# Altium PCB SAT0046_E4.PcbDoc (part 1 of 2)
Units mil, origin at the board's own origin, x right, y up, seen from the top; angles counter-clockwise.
Board outline 1588 x 1588 mil, 4 copper layers (Top Layer, GND, Inner 1, Bottom Layer); 110 components, 70 nets, 285 pads, 141 vias.
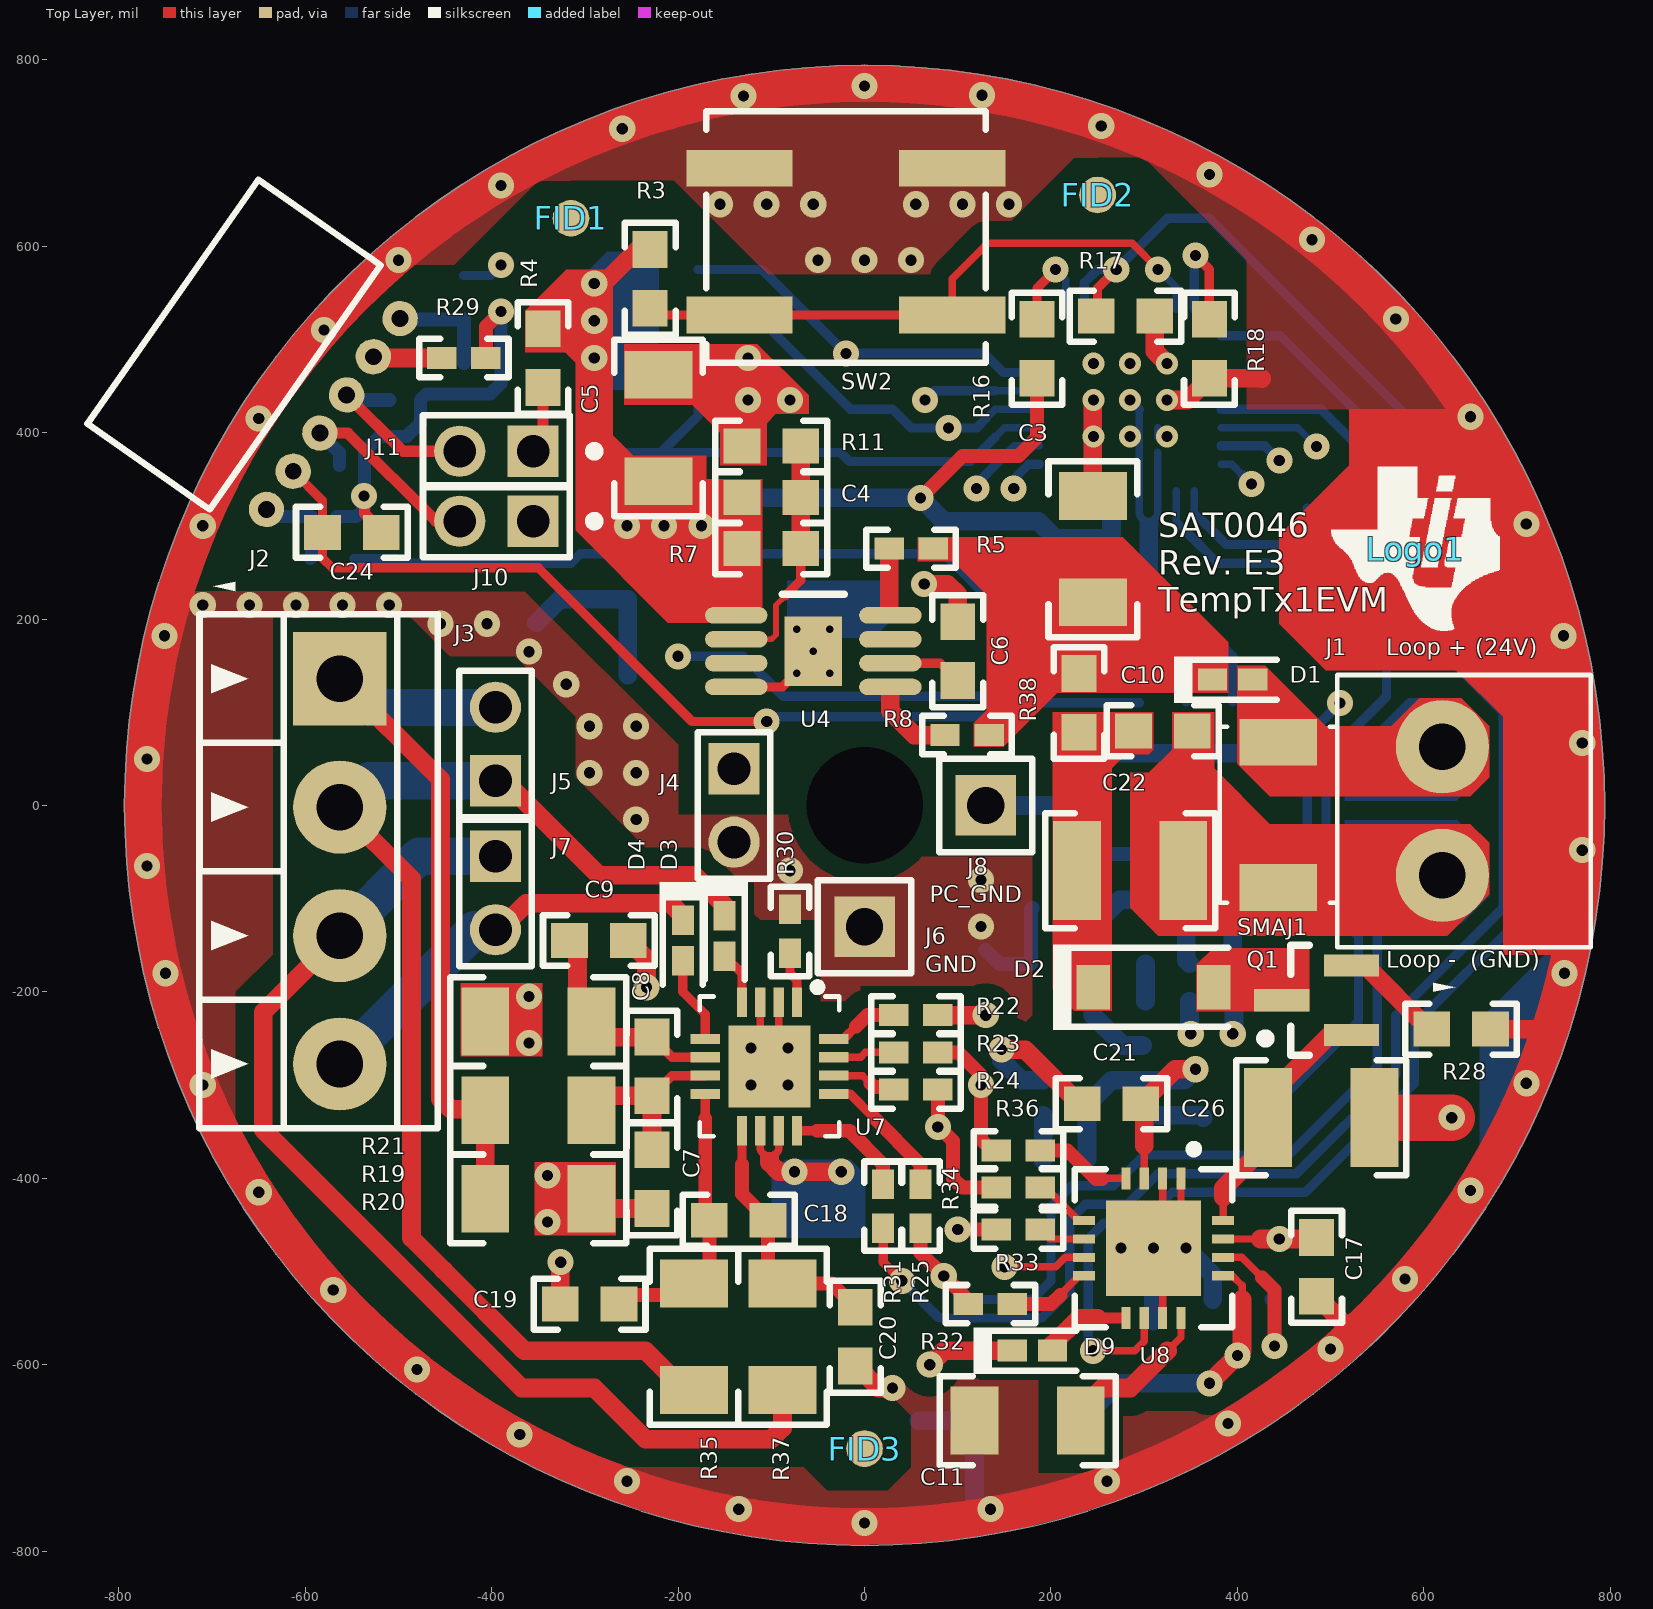
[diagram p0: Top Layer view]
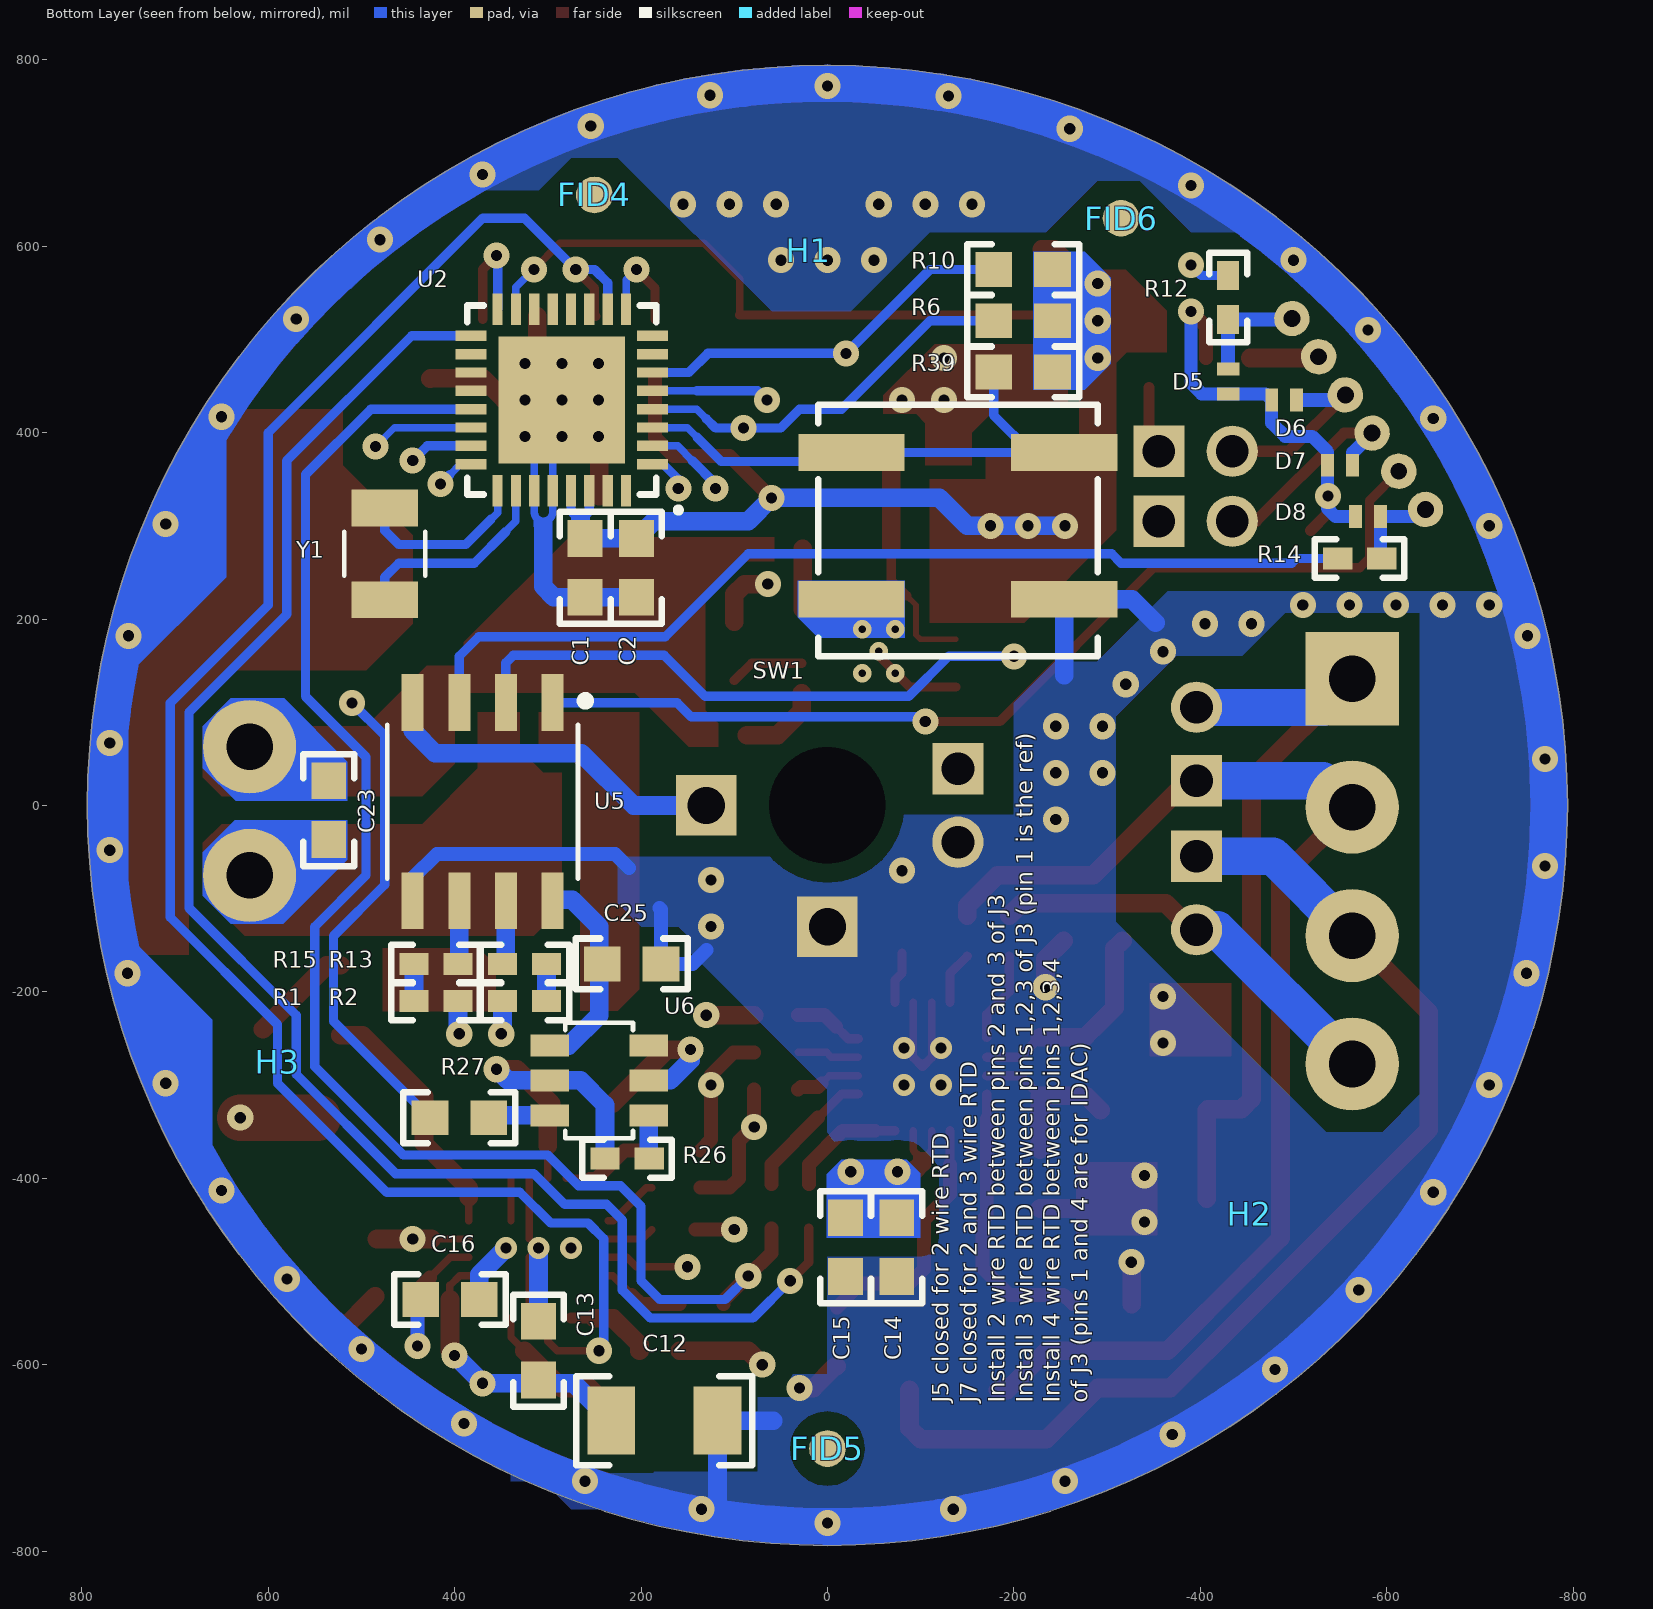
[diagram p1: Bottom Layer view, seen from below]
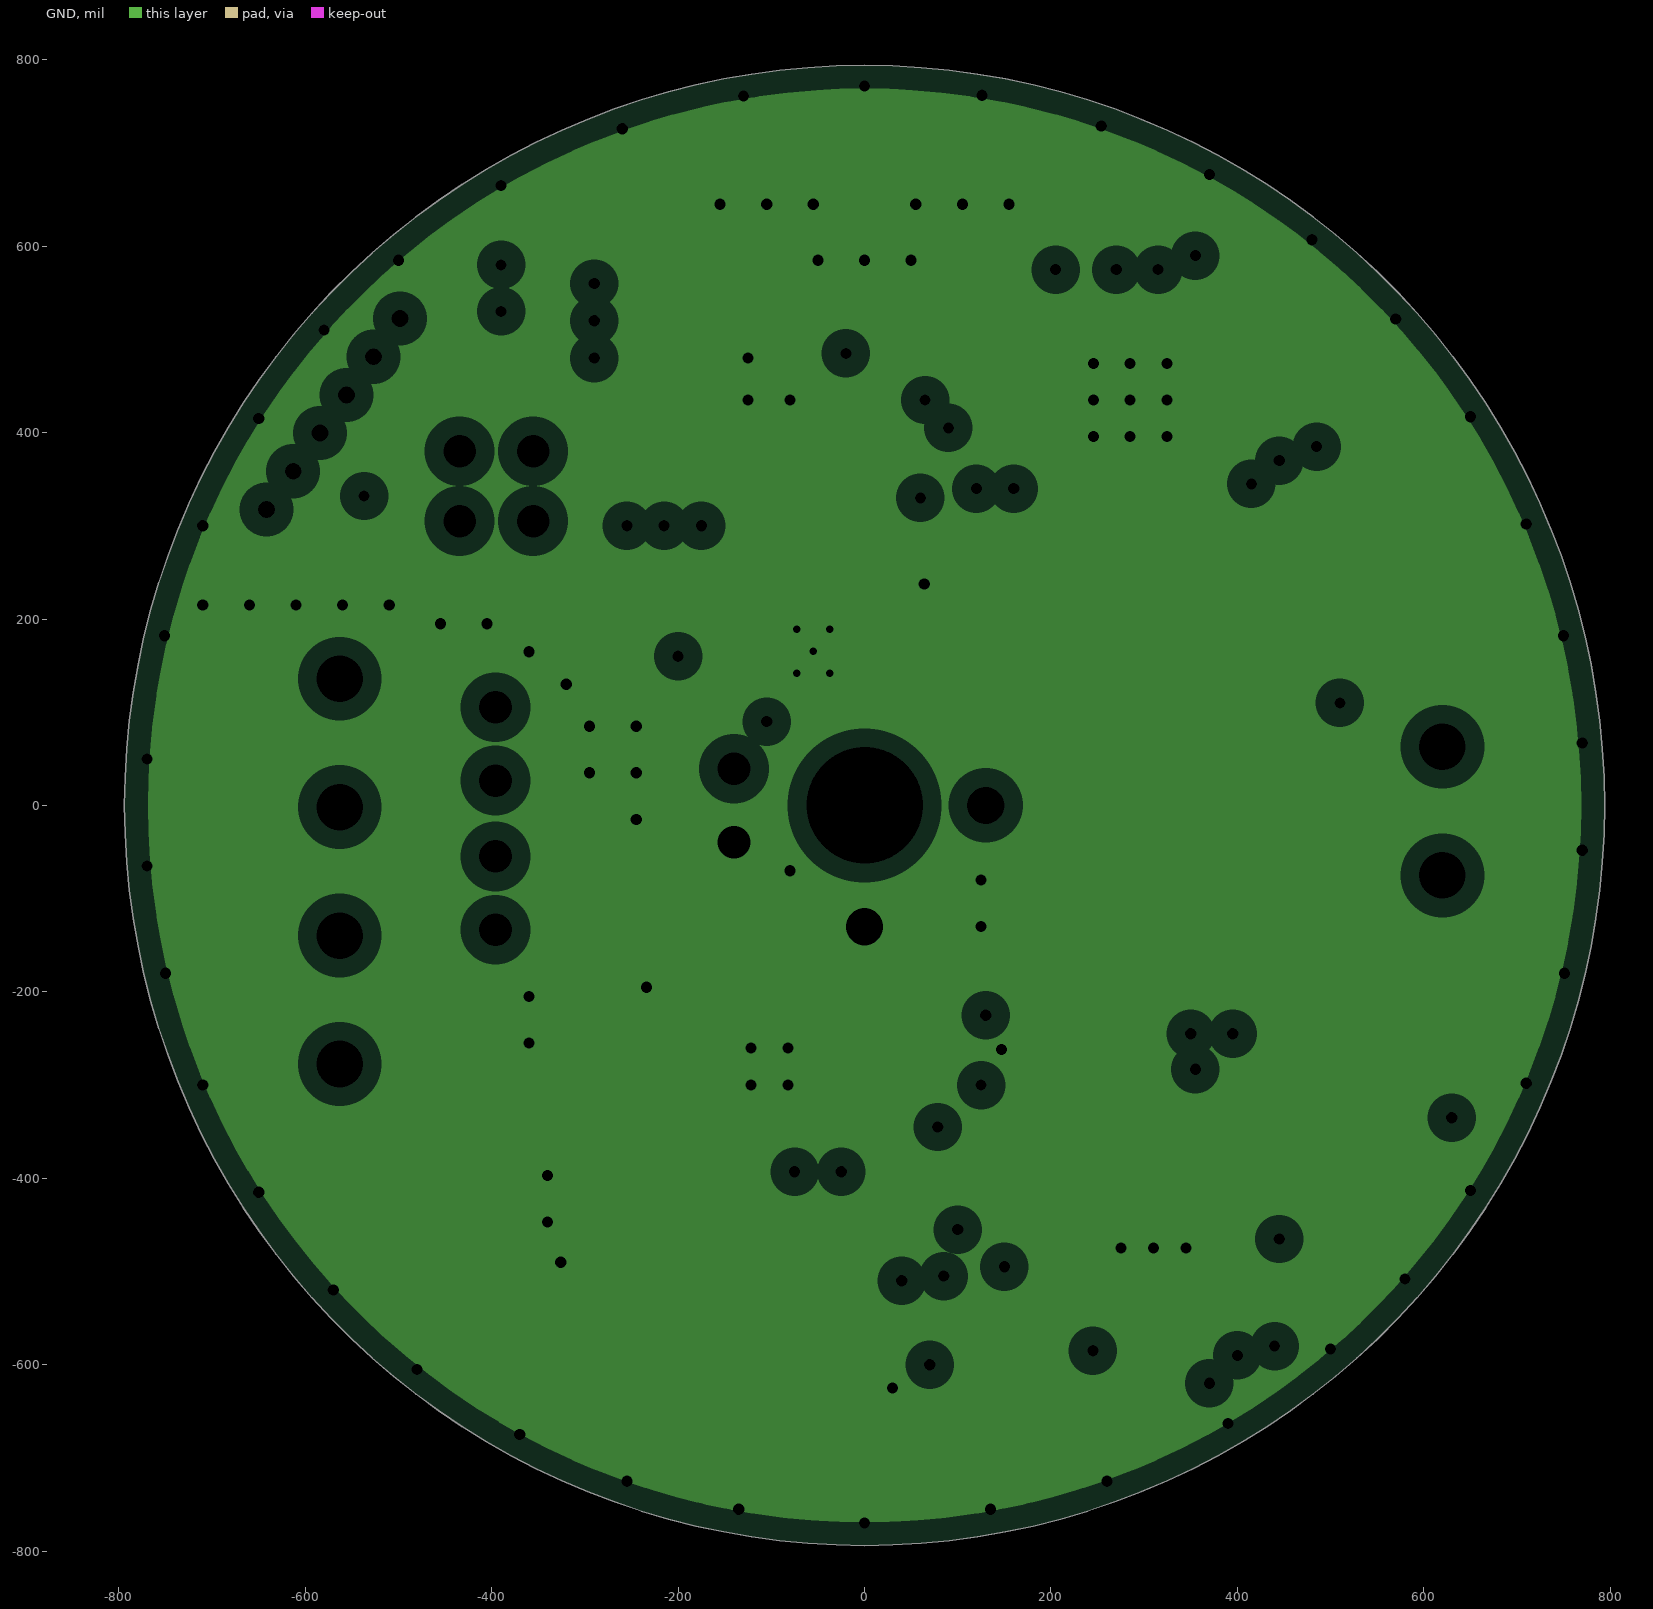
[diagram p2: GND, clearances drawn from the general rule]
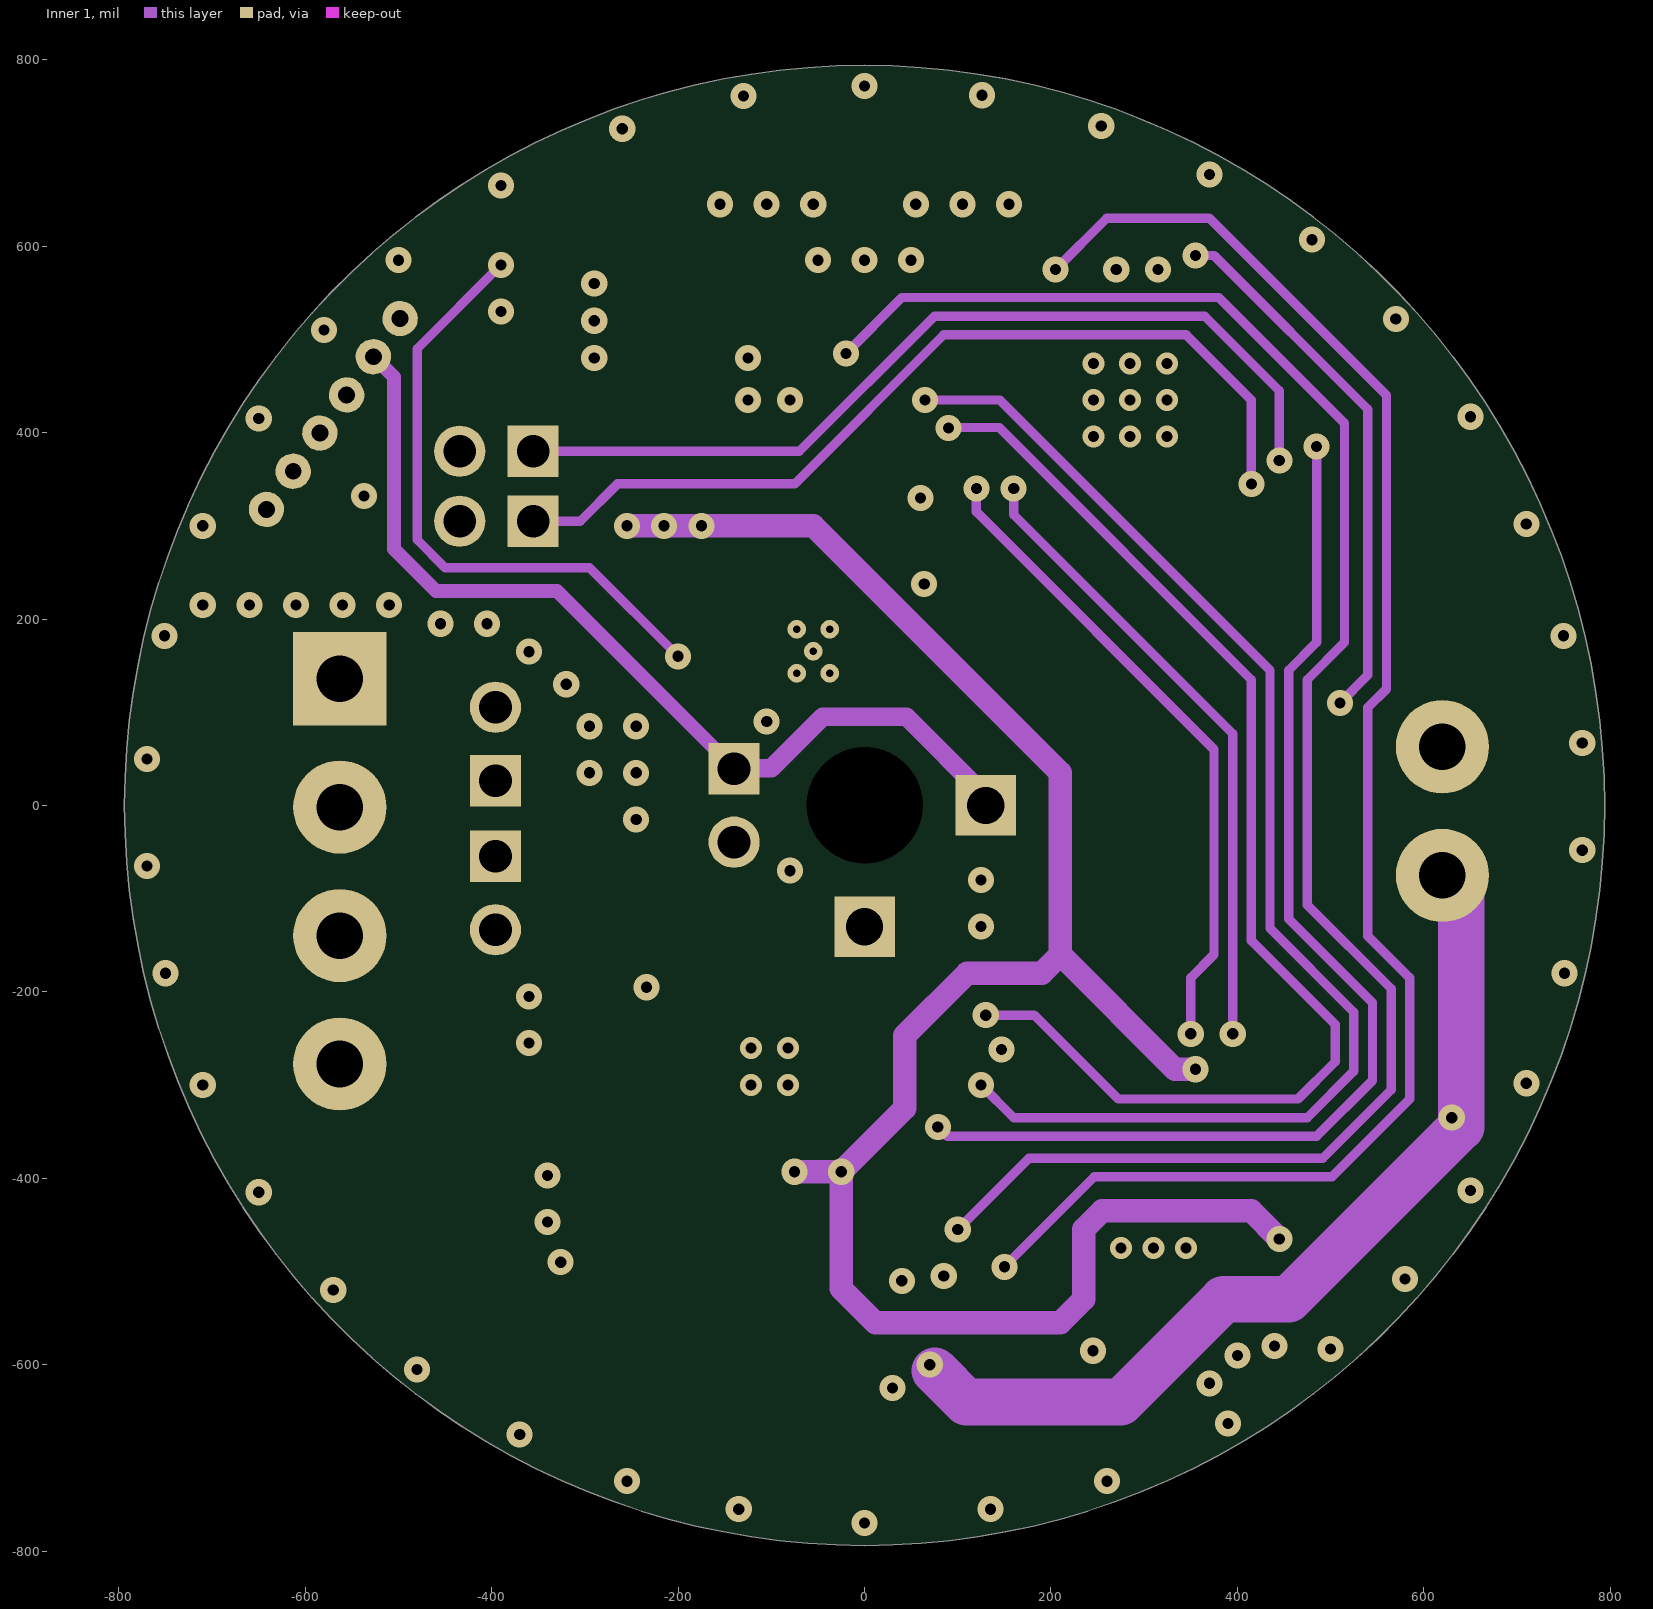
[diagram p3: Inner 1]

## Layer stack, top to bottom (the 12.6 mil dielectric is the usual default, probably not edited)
Top Layer: signal copper 1.4
Dielectric: core 12.6, 370HR, Dk 4.8
GND: plane copper 1.4, net GND
Dielectric: prepreg 12.6, 370HR, Dk 4.8
Inner 1: signal copper 1.4
Dielectric: core 12.6, 370HR, Dk 4.8
Bottom Layer: signal copper 1.4

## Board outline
0,-794 cw(c0,0) -794,0 cw(c0,0) 0,794 cw(c0,0) 794,0 cw(c0,0)

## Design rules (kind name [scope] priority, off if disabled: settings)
AcuteAngle [All] p1: minimum=4.50000000000000E+0001 checktracksonly=FALSE
AssemblyTestPointUsage [All] p1: valid=2
Clearance Clearance_GND_Poly [InPolygon] p1: gap=20
Clearance U2 [InComponent('U2')] p2: gap=8.6
Clearance NetC4_1 [InNet('NetC4_1')] p3: gap=6.09
Clearance U4 [InComponent('U4')] p4: gap=7.87
Clearance U7 [InComponent('U7')] p5: gap=8.6
Clearance U8 [InComponent('U8')] p6: gap=9.8
Clearance Clearance_BoardEdge_MountingHoles [OnCopper and InComponentClass('Mounting Holes') vs IsKeepOut] p7 off: gap=40
Clearance Clearance_BoardEdge_Poly [OnCopper and InPoly vs IsKeepOut] p8 off: gap=25
Clearance Clearance_BoardEdge [OnCopper and Not InComponentClass('Logo') and not InComponentClass('FiducialMark') and not InRegion(1000,500,4000,800) and Not IsKeepout vs IsKeepOut] p9 off: gap=20
Clearance [All] p10: gap=10
ComponentClearance ComponentClearance_Logo [InComponentClass(Logo)] p1 off: gap=50 collisioncheckmode=3 verticalgap=10 showdistances=FALSE
ComponentClearance ComponentClearance_ScrewToNut [(HasFootprint('NY PMS 440 0025 PH')) vs (HasFootprint('Keystone_1902C'))] p2 off: gap=5 collisioncheckmode=3 verticalgap=10 showdistances=FALSE
ComponentClearance ComponentClearance_MountingHoles [InComponentClass('Mounting Holes')] p3 off: gap=250 collisioncheckmode=3 verticalgap=100000 showdistances=FALSE
ComponentClearance ComponentClearance_SmallPassives [HasFootprint('0201*') or HasFootprint('0402*') or HasFootprint('0508') or HasFootprint('0603*') or HasFootprint('0612') or HasFootprint('0805*') or HasFootprint('0815*') or HasFootprint('0830*') or HasFootprint('1206*') or HasFootprint('1210*') or HasFootprint('1808*') or HasFootprint('1812*') or HasFootprint('1825*') or HasFootprint('2010*') or HasFootprint('2220*') or HasFootprint('2225*') or HasFootprint('2512*') or HasFootprint('2728*') or HasFootprint('3518*') vs HasFootprint('0201*') or HasFootprint('0402*') or HasFootprint('0508') or HasFootprint('0603*') or HasFootprint('0612') or HasFootprint('0805*') or HasFootprint('0815*') or HasFootprint('0830*') or HasFootprint('1206*') or HasFootprint('1210*') or HasFootprint('1808*') or HasFootprint('1812*') or HasFootprint('1825*') or HasFootprint('2010*') or HasFootprint('2220*') or HasFootprint('2225*') or HasFootprint('2512*') or HasFootprint('2728*') or HasFootprint('3518*')] p4 off: gap=20 collisioncheckmode=3 verticalgap=10 showdistances=FALSE
ComponentClearance ComponentClearance_THtoSMT [IsThruComponent vs IsSMTComponent] p5 off: gap=100 collisioncheckmode=3 verticalgap=100000 showdistances=FALSE
ComponentClearance ComponentClearance_THtoTH [IsThruComponent vs IsThruComponent] p6 off: gap=118.11 collisioncheckmode=3 verticalgap=100000 showdistances=FALSE
ComponentClearance [All] p7 off: gap=40 collisioncheckmode=3 verticalgap=10 showdistances=FALSE
DiffPairsRouting [All] p1: maxlimit=100 minlimit=10 mostfreqgap=10 maxuncoupledlength=1000
FabricationTestPointUsage TestPointUsage [All] p1: valid=2 allowmultiple=FALSE
FabricationTestpoint Testpoint [All] p1: side=3 testpointundercomponent=TRUE minsize=40 maxsize=100 preferedsize=60 minholesize=0 maxholesize=40 preferedholesize=32 testpointgrid=1 allowsidetop=TRUE allowsidebottom=TRUE usegrid=TRUE gridtolerance=0.01
FanoutControl Fanout_LCC [IsLCC] p1: bgadir=Out bgaviamode=Centered fanoutstyle=Auto fanoutdirection=Alternating viagrid=1 // Fanout_LCC (Default Rule)
FanoutControl Fanout_BGA [IsBGA] p2: bgadir=Out bgaviamode=Centered fanoutstyle=Auto fanoutdirection=Alternating viagrid=1 // Fanout_BGA (Default Rule)
FanoutControl Fanout_Default [All] p4: bgadir=Out bgaviamode=Centered fanoutstyle=Auto fanoutdirection=Alternating viagrid=1 // Fanout_Default (Default Rule)
FanoutControl Fanout_Small [(CompPinCount < 5)] p5: bgadir=Out bgaviamode=Centered fanoutstyle=Auto fanoutdirection=OutThenIn viagrid=1 // Fanout_Small (Default Rule)
HoleSize "U4 Hole" [(InNet('GND') AND InComponent('U4'))] p1: absolutevalues=TRUE maxlimit=100 minlimit=5 maxpercent=80.000 minpercent=20.000
HoleSize [All] p2: absolutevalues=TRUE maxlimit=251 minlimit=8 maxpercent=80.000 minpercent=20.000
MinimumAnnularRing "U8 AnnularRing" [(InNet('GND') AND InComponent('U8'))] p1: minimumring=5
MinimumAnnularRing "U2 AnnularRing" [(InNet('GND') AND InComponent('U2'))] p2: minimumring=5.9
MinimumAnnularRing "U7 AnnularRing" [(InNet('GND') AND InComponent('U7'))] p3: minimumring=3
MinimumAnnularRing "U4 AnnularRing" [(InNet('GND') AND InComponent('U4'))] p4: minimumring=3
MinimumAnnularRing [All] p5: minimumring=5
MinimumSolderMaskSliver MinimumSolderMaskSliver_Logo [InComponentClass('Logo') vs InComponentClass('Logo')] p1: minsoldermaskwidth=0.7
MinimumSolderMaskSliver [All] p2: minsoldermaskwidth=5
PlaneClearance [All] p1: clearance=20
PlaneConnect [All] p1: planeconnectstyle=Direct reliefexpansion=10 reliefentries=4 reliefconductorwidth=10 reliefairgap=10
PolygonConnect [All] p1: connectstyle=Direct reliefconductorwidth=10 reliefentries=4 polygonreliefangle="90 Angle" airgapwidth=10
RoutingVias [All] p1: holewidth=16 width=34 viastyle="Through Hole" minholewidth=5 minwidth=15 maxholewidth=40 maxwidth=65
SMDToCorner [All] p1 off: distance=30000
SilkToSilkClearance [All] p1: silktosilkclearance=0
SilkscreenOverComponentPads [All] p1: minsilkscreentomaskgap=1
SolderMaskExpansion [All] p1: expansion=1
Width [All] p1: maxlimit=100 minlimit=6 preferedwidth=10 checkconnectedcopper=TRUE
13 further rules are at their usual default settings.

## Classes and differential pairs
component class Header: J6 J8
component class Logo: Logo1
component class Hardware: FID1 FID2 FID3 FID4 FID5 FID6 H1 H2 H3 Logo1 ZZ1 ZZ2 ZZ3 ZZ4 ZZ5 ZZ6
component class FiducialMark: FID1 FID2 FID3 FID4 FID5 FID6
component class AssemblyNote: ZZ1 ZZ2 ZZ3 ZZ4 ZZ5 ZZ6
component class SAT0046_E3_Temp_Transmitter_System: C3 C4 C5 C6 C7 C8 C9 C10 C11 C12 C13 C14 C15 C16 C17 C18 C19 C20 C21 C22 C23 C26 D1 D2 D3 D4 D9 J1 J3 J5 J7 Q1 R5 R7 R8 R11 R19 R20 R21 R22 R23 R24 R25 R28 R30 R31 R32 R33 R34 R35 R36 R37 R38 SMAJ1 U4 U7 U8
component class SAT0046_E3_MSP430: C1 C2 C24 C25 D5 D6 D7 D8 J2 J4 J6 J8 J10 J11 R1 R2 R3 R4 R6 R10 R12 R13 R14 R15 R16 R17 R18 R26 R27 R29 R39 SW1 SW2 U2 U5 U6 Y1

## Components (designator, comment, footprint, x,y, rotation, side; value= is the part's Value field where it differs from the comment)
C1 "C0603X104K4RACTU" 0603 260,255 r270 bottom
C2 "C0603X104K4RACTU" 0603 205,255 r90 bottom
C3 "12065C334KAT2A" 1206 245,275 r90 top
C4 "C0603C103J5RACTU" 0603 -100,330.5 r180 top
C5 "GRM31CR71C106KAC7L" 1206 -221,405 r90 top
C6 "C0603C103J5RACTU" 0603 100,165.5 r90 top
C7 "Used in BOM report" 0603 -228,-401 r270 top
C8 "C0603C183K1RACTU" 0603 -228,-280 r90 top
C9 "Used in BOM report" 0603 -285,-145 r0 top
C10 "C0603C103J5RACTU" 0603 320,80 r0 top
C11 "GRM31MR71H394KA01L" 1206 175,-660 r180 top
C12 "C1206C224J5RACTU" 1206 175,-660 r180 bottom
C13 "C0603C682J5RACTU" 0603 310,-585 r90 bottom
C14 "C0603X104K4RACTU" 0603 -74.4,-473.98 r270 bottom
C15 "C0603X104K4RACTU" 0603 -19.4,-473.98 r270 bottom
C16 "C0603C102J5RACTU" 0603 405,-530 r180 bottom
C17 "C0603X104K4RACTU" 0603 485,-495 r270 top
C18 "C0603C273K1RACTU" 0603 -135,-445 r180 top
C19 "Used in BOM report" 0603 -295,-535 r180 top
C20 "Used in BOM report" 0603 -10,-570 r270 top
C21 "C0603X104K4RACTU" 0603 265,-320 r180 top
C22 "GRM32ER71H106KA12L" 1210 285,-70 r0 top
C23 "C1608X7R2A103K" 0603 535,-5 r270 bottom
C24 "C0603X104K4RACTU" 0603 -550,293 r0 top
C25 "C0603X104K4RACTU" 0603 210,-170 r180 bottom
C26 "GRM32ER71H106KA12L" 1210 490,-335 r0 top
D1 "ZHCS350TA" SOD-523 395,135 r0 top
D2 "MMSZ4686T1G" SOD-123 310,-195 r0 top
D3 "ZHCS350TA" SOD-523 -150,-140 r270 top
D4 "ZHCS350TA" SOD-523 -195,-145 r270 top
D5 "TPD1E10B06DPYR" DPY0002A_N -430,455 r270 bottom
D6 "TPD1E10B06DPYR" DPY0002A_N -490,435 r0 bottom
D7 "TPD1E10B06DPYR" DPY0002A_N -550,365 r0 bottom
D8 "TPD1E10B06DPYR" DPY0002A_N -580,310 r0 bottom
D9 "ZHCS350TA" SOD-523 180,-585 r0 top
FID1 "Fiducial" Fiducial10-20#1 -315,630 r0 top
FID2 "Fiducial" Fiducial10-20#1 250,655 r0 top
FID3 "Fiducial" Fiducial10-20#1 0,-690 r0 top
FID4 "Fiducial" Fiducial10-20#2 205,675 r180 bottom
FID5 "Fiducial" Fiducial10-20#1 0,-690 r180 bottom
FID6 "Fiducial" Fiducial10-20#3 -270,650 r180 bottom
H1 "SJ61A1" Bumpon_SJ61A1 20,595 r180 bottom
H2 "SJ61A1" Bumpon_SJ61A1 -453,-438 r180 bottom
H3 "SJ61A1" Bumpon_SJ61A1 590,-275 r180 bottom
J1 "ED555/2DS" TERM_BLK_ED555-2DS 620,-75 r90 top
J2 "851-43-006-20-001000" CONN_851-43-006-20-001000 -570,420 r235 top
J3 "ED555/4DS" TERM_BLK_ED555-4DS -563,136 r270 top
J4 "TMM-102-01-T-S" CONN_TMM-102-01-T-S -140,0 r270 top
J5 "TMM-102-01-T-S" CONN_TMM-102-01-T-S -396,66 r90 top
J6 "TSW-101-07-G-S" TSW-101-07-G-S 0,-130 r0 top
J7 "TMM-102-01-T-S" CONN_TMM-102-01-T-S -396,-94 r270 top
J8 "TSW-101-07-G-S" TSW-101-07-G-S 130,0 r0 top
J10 "TMM-102-01-T-S" CONN_TMM-102-01-T-S -395,305 r180 top
J11 "TMM-102-01-T-S" CONN_TMM-102-01-T-S -395,380 r180 top
Logo1 "Texas Instruments" TI_Symbol_Overlay_Small 591,275 r0 top
Q1 "MMBT3904" SOT-23 485,-209 r180 top
R1 "CRCW04020000Z0ED" 0402 420,-210 r0 bottom
R2 "CRCW04020000Z0ED" 0402 325,-210 r180 bottom
R3 "RT0603BRD07100KL" 0603 -230,565 r90 top
R4 "RG1608P-4752-B-T5" 0603 -345,480 r90 top
R5 "CRCW04020000Z0ED" 0402 50,275.5 r0 top
R6 "RT0603BRD07100KL" 0603 -210,520 r180 bottom
R7 "RC0603FR-0721KL" 0603 -100,275.5 r180 top
R8 "CRCW04020000Z0ED" 0402 110,75.5 r180 top
R10 "RT0603BRD07100KL" 0603 -210,575 r180 bottom
R11 "RC0603FR-0712KL" 0603 -100,385.5 r0 top
R12 "CRCW04020000Z0ED" 0402 -430,545 r90 bottom
R13 "CRCW04020000Z0ED" 0402 325,-170 r180 bottom
R14 "CRCW04020000Z0ED" 0402 -571,265 r0 bottom
R15 "CRCW04020000Z0ED" 0402 420,-170 r0 bottom
R16 "RT0603BRD07100KL" 0603 185,490 r270 top
R17 "RT0603BRD07100KL" 0603 280,525 r180 top
R18 "RT0603BRD07100KL" 0603 370,490 r90 top
R19 "ERA-8AEB4121V" 1206 -350,-327 r0 top
R20 "PFC-W1206R-12-3241-B" 1206 -350,-422 r180 top
R21 "ERA-8AEB4121V" 1206 -350,-232 r0 top
R22 "CRCW04020000Z0ED" 0402 55,-225 r0 top
R23 "CRCW04020000Z0ED" 0402 55,-265 r0 top
R24 "CRCW04020000Z0ED" 0402 55,-305 r0 top
R25 "CRCW04020000Z0ED" 0402 60,-430 r270 top
R26 "CRCW04020000Z0ED" 0402 215,-379 r0 bottom
R27 "ERJ-3GEY0R00V" 0603 395,-335 r0 bottom
R28 "CRCW060320R0FKEA" 0603 640,-240 r180 top
R29 "CRCW04020000Z0ED" 0402 -430,480 r180 top
R30 "CRCW040210K0FKEDHP" 0402 -80,-135 r270 top
R31 "CRCW04020000Z0ED" 0402 20,-430 r90 top
R32 "CRCW04020000Z0ED" 0402 135,-535 r0 top
R33 "CRCW04020000Z0ED" 0402 165,-455 r0 top
R34 "CRCW04020000Z0ED" 0402 165,-410 r0 top
R35 "ERA-8AEB4121V" 1206 -183,-570 r90 top
R36 "CRCW04020000Z0ED" 0402 165,-370 r180 top
R37 "ERA-8AEB4121V" 1206 -88,-570 r90 top
R38 "RT0603DRE07200RL" 0603 230,110 r270 top
R39 "RT0603BRD07100KL" 0603 -210,465 r180 bottom
SMAJ1 "SMAJ36CA" SMAJ36CA 444,-10 r90 top
SW1 "KSC222J LFS" "KSC222J LFS" -140,300 r180 bottom
SW2 "KSC222J LFS" "KSC222J LFS" -20,605 r180 top
U2 "MSP430G2513IRHB32R" MSP430G2513IRHB32T 285,435 r270 bottom
U4 "TPS7A4901DGN" DGN0008D_N -55,165.5 r0 top
U5 "ISO7421ED" ISO7421ED 370,4 r0 bottom
U6 "TS5A3160DBVR" TS5A3160DBV 245,-295 r90 bottom
U7 "ADS1220IRVAR" ADS1220IRVAR -102,-280 r180 top
U8 "DAC161S997RGHR" DAC161S997RGHR 310,-475 r0 top
Y1 "NX3215SA-32.768K-STD-MUS-2" XTAL_NX3215SA 475,270 r90 bottom
ZZ1 "Mouse bites are to be located at the 12, 3, 6, and 9 o'clock orientations." AssemblyNote -2100,1630 r0 top
ZZ2 "These assemblies are ESD sensitive, ESD precautions shall be observed." AssemblyNote -2100,1530 r0 top
ZZ3 "These assemblies must be clean and free from flux and all contaminants. Use of no clean flux is not acceptable." AssemblyNote -2100,1430 r0 top
ZZ4 "These assemblies must comply with workmanship standards IPC-A-610 Class 2., unless otherwise specified." AssemblyNote -2100,1330 r0 top
ZZ5 "Assembly: Three bumpons are to be placed where possible to provide a balanced standoff" AssemblyNote -2100,1230 r0 top
ZZ6 "Polygon pour along the board edge is serving as an ESD ring. Soldermask is not to be placed over the ring on either side." AssemblyNote -2100,1130 r0 top

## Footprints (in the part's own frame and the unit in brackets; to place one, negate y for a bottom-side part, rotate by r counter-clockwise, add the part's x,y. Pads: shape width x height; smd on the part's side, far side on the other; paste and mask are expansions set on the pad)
0402 [mm] "0402 from SM-752 data"
  rect 0.8x0.6 smd: 1(-0.6,0) 2(0.6,0)
  silkscreen extent -1.22,-0.52 1.22,0.52, body extent -0.55,-0.3 0.55,0.3, height 0.6
0603 [mm] "0603 from SM-752 data"
  rect 1x0.95 smd: 1(-0.8,0) 2(0.8,0)
  silkscreen extent -1.52,-0.69 1.52,0.69, body extent -0.87,-0.47 0.87,0.47, height 0.85
1206 [mm] "1206 from SM-752 data"
  rect 1.3x1.85 smd: 1(-1.45,0) 2(1.45,0)
  silkscreen extent -2.4,-1.21 2.4,1.21, body extent -1.7,-0.9 1.7,0.9, height 1.35
1210 [mm] "1210 from SM-752 data"
  rect 1.3x2.7 smd: 1(-1.45,0) 2(1.45,0)
  silkscreen extent -2.32,-1.57 2.32,1.57, body extent -1.7,-1.35 1.7,1.35, height 1.35
ADS1220IRVAR [mm] "Low-Power, Low-Noise, 24-Bit, Analog-to-Digital Converter for Small-Signal Sensors"
  rect 0.28x0.8 smd: 1(-0.75,-1.75) 2(-0.25,-1.75) 3(0.25,-1.75) 4(0.75,-1.75) 9(0.75,1.75) 10(0.25,1.75) 11(-0.25,1.75) 12(-0.75,1.75)
  rect 0.8x0.28 smd: 5(1.75,-0.75) 6(1.75,-0.25) 7(1.75,0.25) 8(1.75,0.75) 13(-1.75,0.75) 14(-1.75,0.25) 15(-1.75,-0.25) 16(-1.75,-0.75)
  rect 2.24x2.24 smd: 17(0,0)
  silkscreen extent -1.9,-2.25 1.9,1.91, body extent -1.8,-1.8 1.8,1.8, height 1.01
AssemblyNote [mil] "Assembly Note"
Bumpon_SJ61A1 [mil] "3M Cylindrical Bumpon black"
  round 1 on Mech4: 0(0,0)
  body extent -156,-155 156,156, height 201
CONN_851-43-006-20-001000 [mil] "Mill-Max"
  round 38 hole 18: 1(125,0) 2(75,0) 3(25,0) 4(-25,0) 5(-75,0) 6(-125,0)
  silkscreen extent -160,-210 160,-50, body extent -157,-210 157,8, height 87
CONN_TMM-102-01-T-S [mil] "SAMTEC"
  rect 55x55 hole 35: 1(-39.37,0)
  round 55 hole 35: 2(39.37,0)
  silkscreen extent -79,-39 79,39, body extent -79,-39 79,39, height 185
DAC161S997RGHR [mm] "IC DAC 16BIT SPI/SRL 16WQFN"
  rect 0.25x0.6 smd: 1(0.75,1.9) 2(0.25,1.9) 3(-0.25,1.9) 4(-0.75,1.9) 9(-0.75,-1.9) 10(-0.25,-1.9) 11(0.25,-1.9) 12(0.75,-1.9)
  rect 0.6x0.25 smd: 5(-1.9,0.75) 6(-1.9,0.25) 7(-1.9,-0.25) 8(-1.9,-0.75) 13(1.9,-0.75) 14(1.9,-0.25) 15(1.9,0.25) 16(1.9,0.75)
  rect 2.6x2.6 smd: 17(0,0)
  silkscreen extent -2.15,-2.15 2.15,2.8, body extent -2.05,-2.05 2.05,2.05, height 0.81
DGN0008D_N [mm] "TSOP, 8-Leads, Body 3x3mm, Pitch 0.65mm, Thermal Pad 1.89x1.57mm, IPC Medium Density"
  oval 1.7x0.45 smd: 1(-2.1,0.975) 2(-2.1,0.325) 3(-2.1,-0.325) 4(-2.1,-0.975) 5(2.1,-0.975) 6(2.1,-0.325) 7(2.1,0.325) 8(2.1,0.975)
  rect 1.57x1.89 smd: 9(0,0)
  silkscreen extent -0.85,1.55 0.85,1.55, body extent -2.45,-1.5 2.45,1.5, height 0.94
DPY0002A_N [mm] "DFN, 2-Leads, Body 1.0x0.6x0.4mm, IPC Medium Density"
  rect 0.35x0.62 smd: 1(-0.34,0) 2(0.34,0)
  body extent -0.5,-0.3 0.5,0.3, height 0.4
Fiducial10-20#1 [mm]
  round 1 smd paste-0.5 mask+0.5: 1(0,0)
Fiducial10-20#2 [mm]
  round 1 smd paste-0.5 mask+0.5: 1(-1.143,-0.508)
Fiducial10-20#3 [mm]
  round 1 smd paste-0.5 mask+0.5: 1(1.143,-0.508)
ISO7421ED [mm] "IC DGTL ISO 2CH LOGIC 8SOIC"
  rect 0.6x1.55 smd mask+0.07: 1(-1.905,-2.7) 2(-0.635,-2.7) 3(0.635,-2.7) 4(1.905,-2.7) 5(1.905,2.7) 6(0.635,2.7) 7(-0.635,2.7) 8(-1.905,2.7)
  silkscreen extent -2.91,-2.86 2.6,2.1, body extent -2.45,-3 2.45,3, height 1.7
"KSC222J LFS" [mm]
  rect 2.9x1 smd mask+0: 1(-2.9,2) 2(-2.9,-2) 3(2.9,-2) 4(2.9,2)
  silkscreen extent -3.81,-3.56 3.81,3.3, body extent -3.3,-3.05 3.3,3.05, height 3.51
MSP430G2513IRHB32T [mm] "MSP430G2x13 Mixed Signal Microcontroller (Value Line)"
  rect 0.28x0.85 smd mask+0: 1(1.75,2.475) 2(1.25,2.475) 3(0.75,2.475) 4(0.25,2.475) 5(-0.25,2.475) 6(-0.75,2.475) 7(-1.25,2.475) 8(-1.75,2.475) 17(-1.75,-2.475) 18(-1.25,-2.475) 19(-0.75,-2.475) 20(-0.25,-2.475) 21(0.25,-2.475) 22(0.75,-2.475) 23(1.25,-2.475) 24(1.75,-2.475)
  rect 0.85x0.28 smd mask+0: 9(-2.475,1.75) 10(-2.475,1.25) 11(-2.475,0.75) 12(-2.475,0.25) 13(-2.475,-0.25) 14(-2.475,-0.75) 15(-2.475,-1.25) 16(-2.475,-1.75) 25(2.475,-1.75) 26(2.475,-1.25) 27(2.475,-0.75) 28(2.475,-0.25) 29(2.475,0.25) 30(2.475,0.75) 31(2.475,1.25) 32(2.475,1.75)
  rect 3.45x3.45 smd paste+0 mask+0: 33(0,0)
  silkscreen extent -2.58,-2.58 3.02,3.2, body extent -2.51,-2.51 2.51,2.51, height 0.8
SMAJ36CA [mil] "DIODE TVS 36V 400W BI 5% SMD"
  rect 50x83 smd: 1(-78,0) 2(78,0)
  silkscreen extent -94,-63 94,63, body extent -102,-51 102,51, height 95
SOD-123 [mm] "On Semi recommended land pattern"
  rect 0.915x1.22 smd: 1(-1.637,0) 2(1.637,0)
  silkscreen extent -2.74,-1.17 2.03,1.17, body extent -1.93,-0.9 1.93,0.9, height 1.35
SOD-523 [mm] "NXP Semiconductor recommended land pattern, nominal STEP model"
  rect 0.8x0.6 smd paste-0.05: 1(-0.55,0) 2(0.55,0)
  silkscreen extent -1.6,-0.64 1.2,0.64, body extent -0.8,-0.4 0.8,0.4, height 0.72
SOT-23 [mm] "SOT23, 3-Leads, Body 2.9x1.3mm, Pitch 0.95mm, Lead Span 2.5mm, IPC Medium Density"
  rect 1.5x0.6 smd: 1(-0.95,0.95) 2(-0.95,-0.95) 3(0.95,0)
  silkscreen extent 0.2,-1.5 1.52,1.5, body extent -1.16,-1.45 1.21,1.45, height 1
TERM_BLK_ED555-2DS [mil]
  round 100 hole 50: 1(0,0) 2(138,0)
  silkscreen extent -125,-159 215,113, body extent -69,-150 207,106, height 323
TERM_BLK_ED555-4DS [mm]
  rect 2.54x2.54 hole 1.27: 1(0,0)
  round 2.54 hole 1.27: 2(3.5,0) 3(7,0) 4(10.5,0)
  silkscreen extent -2.64,-3.83 12.25,2.67, body extent -1.75,-3.8 12.25,2.7, height 8.2
TI_Symbol_Overlay_Small [mil]
  silkscreen extent -90,-88 91,88
TS5A3160DBV [mm] "1-Ohm SPDT Analog Switch 5-V/3.3-V Single-Channel 2:1 Multiplexer/Demultiplexer"
  rect 0.6x1.05 smd mask+0: 1(-0.95,-1.35) 2(0,-1.35) 3(0.95,-1.35) 4(0.95,1.35) 5(0,1.35) 6(-0.95,1.35)
  silkscreen extent -1.58,-0.92 1.58,0.92
TSW-101-07-G-S [mm] "Samtec 100mil, 1pos, 230 mil above insulator"
  rect 1.65x1.65 hole 1.016 mask+0: 1(0,0)
  silkscreen extent -1.27,-1.27 1.27,1.27, body extent -1.27,-1.27 1.27,1.27, height 8.38
XTAL_NX3215SA [mm] "NDK recommended land pattern"
  rect 1x1.8 smd: 1(-1.25,0) 2(1.25,0)
  silkscreen extent -0.6,-1.1 0.6,1.1, body extent -1.65,-0.8 1.65,0.8, height 0.9

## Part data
C1 C2 C14 C15 C17 C21 C24 C25: "CAP, CERM, 0.1uF, 16V, +/-10%, X7R, 0603"
C3: "CAP, CERM, 0.33uF, 50V, +/-10%, X7R, 1206"
C4 C6 C10: "CAP, CERM, 0.01uF, 50V, +/-5%, X7R, 0603"
C5: "CAP, CERM, 10uF, 16V, +/-10%, X7R, 1206"
C7 C9: library part C0603C182K1RACTU, "CAP CER 1800PF 100V 10% X7R 0603"
C8: "CAP, CERM, 0.018uF, 100V, +/-10%, X7R, 0603"
C11: "CAP, CERM, 0.39uF, 50V, +/-10%, X7R, 1206"
C12: "CAP, CERM, 0.22uF, 50V, +/-5%, X7R, 1206"
C13: "CAP, CERM, 6800pF, 50V, +/-5%, X7R, 0603"
C16: "CAP, CERM, 1000pF, 50V, +/-5%, X7R, 0603"
C18: "CAP, CERM, 0.027uF, 100V, +/-10%, X7R, 0603"
C19 C20: library part C0603C272K1RACTU, "CAP CER 2700PF 100V 10% X7R 0603"
C22 C26: "CAP, CERM, 10uF, 50V, +/-10%, X7R, 1210"
C23: "CAP, CERM, 0.01uF, 100V, +/-10%, X7R, 0603"
D1 D3 D4 D9: "Diode, Schottky, 40V, 0.35A, SOD-523"
D2: "Diode, Zener, 3.9V, 500mW, SOD-123"
D5 D6 D7 D8: "ESD in 0402 Package with 10 pF Capacitance and 6 V Breakdown, 1 Channel, -40 to +125 degC, 2-pin X2SON (DPY), Green (RoHS & no Sb/Br)"
FID1 FID2 FID3 FID4 FID5 FID6: "Fiducial mark.  There is nothing to buy or mount."
H1 H2 H3: "Bumpon, Cylindrical, 0.312 X 0.200, Black"
J1: "Terminal Block, 6A, 3.5mm Pitch, 2-Pos, TH"
J2: "Receptacle, 50mil, 6x1, R/A, TH"
J3: "Terminal Block, 6A, 3.5mm Pitch, 4-Pos, TH"
J4 J5 J7 J10 J11: "Header, 2mm, 2x1, Tin, TH"
J6 J8: "Header, TH, 100mil, 1pos, Gold plated, 230 mil above insulator"
Logo1: library part TI_Logo, "Texas Instrument Corporate Signature"
Q1: library part "MMBT3904, Fairchild Semiconductor", "Transistor, NPN, 40V, 0.2A, SOT-23"
R1 R2 R5 R8 R12 R13 R14 R15 R22 R23 R24 R25 R26 R29 R31 R32 R33 R34 R36: "RES, 0 ohm, 5%, 0.063W, 0402"
R3 R6 R10 R16 R17 R18 R39: "RES, 100k ohm, 0.1%, 0.1W, 0603"
R4: "RES, 47.5k ohm, 0.1%, 0.1W, 0603"
R7: "RES, 21.0k ohm, 1%, 0.1W, 0603"
R11: "RES, 12.0k ohm, 1%, 0.1W, 0603"
R19 R21 R35 R37: "RES 4.12K OHM 1/4W .1% 1206 SMD"
R20: library part "66-PFC 12L3.24k-B", "Thin Film Resistors - SMD 3.24K .1% 10ppm"
R27: library part Resistor, "RES 0.0 OHM 1/10W JUMP 0603 SMD"
R28: "RES, 20.0 ohm, 1%, 0.1W, 0603"
R30: library part Resistor, "RES, xxx ohm, x%, xW, [PackageReference]"
R38: "RES, 200 ohm, 0.5%, 0.1W, 0603"
SMAJ1: "DIODE TVS 36V 400W BI 5% SMD"
SW1 SW2: "SWITCH TACTILE SPST-NO 0.05A 32V"
U2: library part MSP430G2513RHB32T, "IC MCU 16BIT 16KB FLASH 32QFN"
U4: "+36V, +150mA, Ultralow-Noise, Positive LINEAR REGULATOR, DGN0008D"
U5: "50 Mbps Low-Power Dual Channels Digital Isolator, 3.3 V / 5 V, -40 to +125 degC, 8-pin SOIC (D), Green (RoHS & no Sb/Br)"
U6: "IC SWITCH SPDT SOT23-6"
U7: "Low-Power, Low-Noise, 24-Bit, Analog-to-Digital Converter for Small-Signal Sensors"
U8: "IC DAC 16BIT SPI/SRL 16WQFN"
Y1: "Crystal, 32.768kHz, 12.5pF, SMD"
ZZ1 ZZ2 ZZ3 ZZ4 ZZ5 ZZ6: library part AssemblyNote

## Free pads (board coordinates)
  round 60 hole 125: 0(0,0)

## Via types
v1: diameter 28, hole 12, Top Layer to Bottom Layer, tented both sides, 120 vias
v2: diameter 23.62, hole 11.81, Top Layer to Bottom Layer, tented both sides, 16 vias
v3: diameter 19.68, hole 7.87, Top Layer to Bottom Layer, tented both sides, 5 vias

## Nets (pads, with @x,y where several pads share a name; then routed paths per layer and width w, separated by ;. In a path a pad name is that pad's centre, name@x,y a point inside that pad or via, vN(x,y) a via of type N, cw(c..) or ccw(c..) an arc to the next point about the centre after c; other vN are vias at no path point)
ADS_DAC_CLK: R23.2 R36.2 U2.5 | length 1661.4
  Top Layer w15: R23.2@78.62,-265 101,-265 125,-289 v1(125,-300) 125,-358.62 R36.2@136.38,-370
  Inner 1 w10: v1(65,435) 145,435 435,145 435,-131.77 525,-221.77 525,-285 475,-335 160,-335 v1(125,-300)
  Bottom Layer w8: 140,445 140.16,444.84 U2.5@187.56,444.84
  Bottom Layer w10: v1(65,435) 75,445 140,445
ADS_DAC_DIN: R24.2 R34.1 U2.22 | length 1482.4
  Top Layer w15: v1@78.62,-343.62 R24.2@78.62,-305 ; v1@79.31,-344.31 95,-360 95,-400 105,-410 R34.1@136.38,-410
  Inner 1 w10: v1(78.62,-345) 88.62,-355 485,-355 545,-295 545,-211.77 455,-121.77 455,145 485,175 v1(485,385)
  Bottom Layer w8: U2.22@382.44,405.47 464.53,405.47 v1(485,385)
ADS_DAC_DOUT: R25.2 R32.1 U2.21 | length 1619.8
  Top Layer w15: R25.2@60,-453.62 60,-480 v1(85,-505) 111.38,-531.38 R32.1@111.38,-535
  Bottom Layer w10: v1(85,-505) 110,-530 180,-530 200,-510 200,-430 222,-408 267.2,-408 300.2,-375 455,-375 550,-280 550,-130 495,-75 495,52 560,117 560,355 489.84,425.16 U2.21@382.44,425.16
ADS_REFN: C8.2 C9.1 R21.2 U7.6 | length 234.5
  Top Layer w10: C8.2@-228,-248.5 -206.5,-270 U7.6@-170.9,-270
  Top Layer w20: C9.1@-316.5,-145 -308,-153.5 -308,-216.91 R21.2@-292.91,-232 -276.41,-248.5 C8.2@-228,-248.5
ADS_REFP: C7.1 C8.1 R19.2 U7.7 | length 195.3
  Top Layer w10: C8.1@-228,-311.5 -206.5,-290 U7.7@-170.9,-290
  Top Layer w20: R19.2@-292.91,-327 -277.41,-311.5 C8.1@-228,-311.5 C7.1@-228,-369.5
ERR_LVL: R17.2 U2.10 U8.10 | length 1990.2
  Top Layer w8: v1(245,-585) 290,-585 300.16,-574.84 U8.10@300.16,-549.8
  Top Layer w10: R17.2@248.5,525 250,526.5 250,555 v1(270,575)
  Bottom Layer w8: v1@240,-580 v1(245,-585)
  Bottom Layer w10: U2.10@235.79,532.44 235.79,560.79 250,575 v1(270,575) 325,630 370,630 600,400 600,215 705,110 705,-120 590,-235 590,-297.99 472.99,-415 330,-415 297,-448 257,-448 240,-465 240,-550 v1@240,-580
GAIN_CAL_INTERRUPT: R3.1 SW2.1 SW2.4 U2.15 | length 664.7
  Top Layer w8: SW2.1@94.17,526.26 94.17,565.17 132,603 287,603 v1(315,575)
  Top Layer w10: R3.1@-230,533.5 -222.76,526.26 SW2.4@-134.17,526.26 SW2.1@94.17,526.26
  Bottom Layer w8: v1(315,575) 334.21,555.79 U2.15@334.21,532.44
GND: C1.2 C2.1 C3.2 C5.2 C6.2 C7.2 C9.2 C11.2 C12.2 C13.2 C14.2 C15.2 C16.2 C17.2 C19.2 C20.2 C21.2 C25.2 J4.2 J6.1 R11.1 R17.1 R18.1 R20.1 R21.1 R28.1 R30.1 SW1.2 SW1.3 SW2.2 SW2.3 U2.27 U2.28 U2.33 U4.4 U4.9 U5.5 U6.2 U7.2 U7.3 U7.17 U8.1 U8.2 U8.11 U8.17 | length 12317.2
  Top Layer w8: U7.17@-111.84,-270.16 U7.3@-111.84,-211.1 ; U7.17@-92.16,-270.16 U7.2@-92.16,-211.1 ; v2(310,-475) 319.84,-484.84 U8.11@319.84,-549.8 ; U8.17@319.84,-465.16 U8.2@319.84,-400.2 ; U8.17@339.53,-445.47 U8.1@339.53,-400.2
  Top Layer w10: U4.4@-137.68,127.11 -88.39,127.11 U4.9@-55,160.5 ; U7.17@-111.84,-270.16 U7.17@-102,-280 U7.17@-92.16,-270.16
  Top Layer w20: C19.2@-326.5,-535 -326.5,-490.5 v1(-326,-490) ; R20.1@-291.91,-437 -287.41,-432.5 C7.2@-228,-432.5 ; C9.2@-253.5,-145 -234,-164.5 v1(-234,-195) ; C20.2@-10,-601.5 -8.5,-601.5 15,-625 v1(30,-625) ; v1(64,237.5) 89,237.5 100,226.5 C6.2@100,197 ; v1(147,-262) 172.57,-262 C21.2@230.57,-320 ; C3.2@245,332.09 245,434.37 v2(245.63,435) ; R17.1@311.5,525 311.5,487.24 v2(324.37,474.37) ; v2(324.37,435) 346.5,435 R18.1@370,458.5 425.5,458.5 426,458 ; C17.2@485,-526.5 522.48,-563.98 529.61,-563.98 ; 633.67,-435 637.36,-438.69 ; R28.1@671.5,-240 735.16,-240 ; 672.67,-380 673.55,-380.88 ; 697.45,-325 700.74,-328.28 ; 702.58,-315 704.69,-317.12 ; 743.38,-195 747.79,-199.41
  Top Layer w40: v1@0,-773.85 cw(c0.15,0.38) v1@-0.02,774.6 ; v1@0.02,-773.6 ccw(c-0.15,0.62) 529.61,-563.98 ccw(c-0.15,0.62) 637.36,-438.69 ccw(c-0.15,0.62) 673.55,-380.88 ccw(c-0.15,0.62) 700.74,-328.28 ccw(c-0.15,0.62) 713.54,-299.49 ccw(c-0.15,0.62) 747.79,-199.41 ccw(c-0.15,0.62) v1@0,774.85
  Bottom Layer w8: U2.33@294.84,425.16 U2.28@294.84,337.56 294.84,315.16 ccw(c304.69,314.85) 314.53,315.47 U2.33@314.53,379 ; U2.33@314.53,395.63 U2.33@314.53,405.47
  Bottom Layer w10: v2(285,435) U2.33@294.84,425.16
  Bottom Layer w15: 130,-155 145,-170 C25.2@178.5,-170 178.5,-111.5 180,-110 ; 213,-67 228,-52 419,-52 445,-78 U5.5@445,-101.3
  Bottom Layer w20: -352,196 -326.74,221.26 SW1.3@-254.17,221.26 -254.17,139.83 ; 58.3,-660 C12.2@117.91,-660 117.91,-760.96 ; v1(147,-262) 147,-273.51 168.49,-295 U6.2@191.85,-295 ; C2.1@205,223.5 C1.2@260,223.5 293.5,223.5 305,235 305,299 ; C13.2@310,-553.5 v2(310,-475) ; v2(345,-475) 373.5,-503.5 C16.2@373.5,-530
  Bottom Layer w40: v1@0,-773.85 cw(c0.15,0.38) v1@-0.02,774.6 ; v1@0.02,-773.6 ccw(c-0.15,0.62) 580.36,-511.66 ccw(c-0.15,0.62) v1@0,774.85
  other v1: 0,-770 -135,-755 135,-755 -255,-725 260,-725 -370,-675 390,-663 -480,-605 500,-583 -570,-520 580,-508 -340.09,-447 -650,-415 650,-413 -340.09,-397 -710,-300 710,-298 -360,-255 -360,-205 -750,-180 751,-180 125,-130 125,-80 -80,-70 -770,-65 770,-48 -245,-15 -295,35 -245,35 -770,50 770,67 -295,85 -245,85 -320,130 -360,165 -751,182 750,182 -455,195 -405,195 -710,215 -660,215 -610,215 -560,215 -510,215 -710,300 710,302 -650,415 650,417 -125,435 -80,435 -125,480 -580,510 570,522 -500,585 -50,585 0,585 50,585 480,607 -155,645 -105,645 -55,645 55,645 105,645 155,645 -390,665 370,677 -260,726 254,729 -130,761 126,762 0,772
  other v2: 275,-475 -121.68,-299.68 -82.32,-299.68 -121.68,-260.32 -82.32,-260.32 245.63,395.63 285,395.63 324.37,395.63 245.63,474.37 285,474.37
  other v3: -72.72,141.88 -37.28,141.88 -55,165.5 -72.72,189.12 -37.28,189.12
LOOP-: C10.2 C22.2 C23.2 C26.2 D9.1 J1.1 SMAJ1.1 | length 1156.3
  Top Layer w20: v1(70,-600) 85,-585 D9.1@158.35,-585
  Top Layer w50: C26.2@547.09,-335 v1(630,-335)
  Inner 1 w50: v1@75.5,-606.5 109,-640 275,-640 385,-530 455,-530 640,-345 640,-95 J1.1@620,-75
LOOP_PWR: C10.1 C22.1 D2.1 R38.2
NADS_CS: R6.1 R22.2 U2.4 | length 1786.8
  Top Layer w20: R22.2@78.62,-225 v1(130,-225)
  Inner 1 w10: v1(90,405) 90.47,405.47 144.53,405.47 415,135 415,-145 505,-235 505,-275 465,-315 272.22,-315 182.22,-225 v1(130,-225)
  Bottom Layer w8: 130,415 140.16,425.16 U2.4@187.56,425.16
  Bottom Layer w10: R6.1@-178.5,520 -110,520 -15,425 30,425 50,405 v1(90,405) 120,405 130,415
NADS_DRDY: R31.1 U2.17 | length 1766.1
  Top Layer w10: R31.1@20,-453.62 20,-490 v1(40,-510)
  Bottom Layer w10: v1(40,-510) 80,-550 190,-550 220,-520 220,-445 237,-428 282,-428 315,-395 463.5,-395 570,-288.5 570,-225 685,-110 685,100 580,205 580,370 446.1,503.9 U2.17@382.44,503.9
NDAC_CS: R10.1 R33.1 U2.6 | length 2365
  Top Layer w15: v1(100,-455) R33.1@141.38,-455
  Inner 1 w10: v1(-20,485) 40,545 380,545 515,410 515,175 475,135 475,-106.77 565,-196.77 565,-305 491.5,-378.5 176.5,-378.5 v1(100,-455)
  Bottom Layer w10: R10.1@-178.5,575 -110,575 v1(-20,485) 128.28,485 148.76,464.53 U2.6@187.56,464.53
NDAC_ERROR: R16.1 U2.9 U8.7 | length 1939.2
  Top Layer w8: v1(150,-495) 205,-495 215.16,-484.84 U8.7@235.2,-484.84
  Top Layer w10: R16.1@185,521.5 185,555 v1@200,570
  Inner 1 w10: v1(150,-495) 246.5,-398.5 501.5,-398.5 585,-315 585,-185 540,-140 540,105 560,125 560,440 370,630 260,630 v1(205,575)
  Bottom Layer w8: v1(205,575) 216.1,563.9 U2.9@216.1,532.44
NetC3_1: C3.1 D1.1 R5.2 R8.1 R38.1
NetC4_1: C4.1 R7.1 R11.2 U4.2 | length 258.1
  Top Layer w6: U4.2@-137.68,178.3 -99.7,178.3 -95,183 -95,215 -85,225
  Top Layer w10: -85,225 -68.5,241.5 R7.1@-68.5,275.5
  Top Layer w20: R7.1@-68.5,275.5 R11.2@-68.5,385.5
NetC6_1: C6.1 U4.6 | length 80.1
  Top Layer w10: U4.6@27.68,152.7 81.3,152.7 C6.1@100,134
NetC11_1: C11.1 U8.12 | length 172.3
  Top Layer w8: 325,-585 339.53,-570.47 U8.12@339.53,-549.8
  Top Layer w20: C11.1@232.09,-660 232.09,-647.91 255,-625 285,-625 325,-585
NetC12_1: C12.1 C13.1 U8.13 | length 340.9
  Top Layer w8: U8.13@384.8,-504.53 394.53,-504.53 405,-515 405,-530
  Top Layer w20: v1(370,-620) 405,-585 405,-530
  Bottom Layer w20: C12.1@232.09,-660 272.09,-620 v1(370,-620) v1(400,-590)
NetC16_1: C16.1 U8.14 | length 181.2
  Top Layer w8: U8.14@384.8,-484.84 404.84,-484.84 426.65,-506.65
  Top Layer w15: 426.65,-506.65 440,-520 v1(440,-580)
  Bottom Layer w15: C16.1@436.5,-530 440,-533.5 v1(440,-580)
NetC18_1: C18.1 C20.1 R37.2 U7.9 | length 270.6
  Top Layer w10: -131.53,-385 U7.9@-131.53,-348.9
  Top Layer w15: -131.53,-385 -131.53,-416.83 -103.5,-444.86 C18.1@-103.5,-445 -103.5,-497.41 R37.2@-88,-512.91 -35.59,-512.91 C20.1@-10,-538.5
NetC18_2: C18.2 C19.1 R35.2 U7.8 | length 301.2
  Top Layer w10: -170.9,-335.9 U7.8@-170.9,-310
  Top Layer w15: C19.1@-263.5,-535 -253.5,-525 -195.09,-525 R35.2@-183,-512.91 -166.5,-496.41 C18.2@-166.5,-445 -170.9,-440.6 -170.9,-335.9
NetC23_1: C23.1 D1.2 J1.2 SMAJ1.2
NetC24_2: C24.2 D5.2 D6.2 D7.2 D8.2 R29.1 | length 464.3
  Top Layer w12: v1@-536.61,332 -536.61,313.11 C24.2@-518.5,295
  Top Layer w15: R29.1@-406.38,480 -406.38,513.62 v1(-390,530)
  Bottom Layer w14: D8.2@-566.61,310 -545,310 -536.61,318.39 -536.61,379.39 -520,396 -491,396 -476.61,410.39 D6.2@-476.61,435 -470,441.61 D5.2@-430,441.61 -401.39,441.61 -390,453 v1(-390,530)
  other v1: -537,332
NetC26_1: C26.1 Q1.1 U8.16 | length 296.3
  Top Layer w8: U8.16@384.8,-445.47 384.8,-420.2
  Top Layer w10: C26.1@437.6,-359 C26.1@437.6,-332.6
  Top Layer w20: 384.8,-420.2 384.8,-410.72 432.91,-362.61 C26.1@432.91,-335 432.91,-312.27 498.78,-246.4 Q1.1@522.4,-246.4
NetD2_2: D2.2 Q1.3
NetD3_1: D3.1 J3.2 J5.1 R35.1 | length 1357.2
  Top Layer w20: J3.2@-563,-1.8 -486,-78.8 -486,-464 -451.68,-498.32 -451.68,-498.43 -365.11,-585 -235,-585 -192.91,-627.09 R35.1@-183,-627.09 ; J5.1@-396,26.63 -386.63,26.63 -285,-75 -182.5,-75 -150,-107.5 D3.1@-150,-118.35
  Bottom Layer w40: J3.2@-563,-5 -531.37,26.63 J5.1@-396,26.63
NetD3_2: D3.2 U7.4 | length 57.1
  Top Layer w10: D3.2@-150,-161.65 -131.53,-180.13 U7.4@-131.53,-211.1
